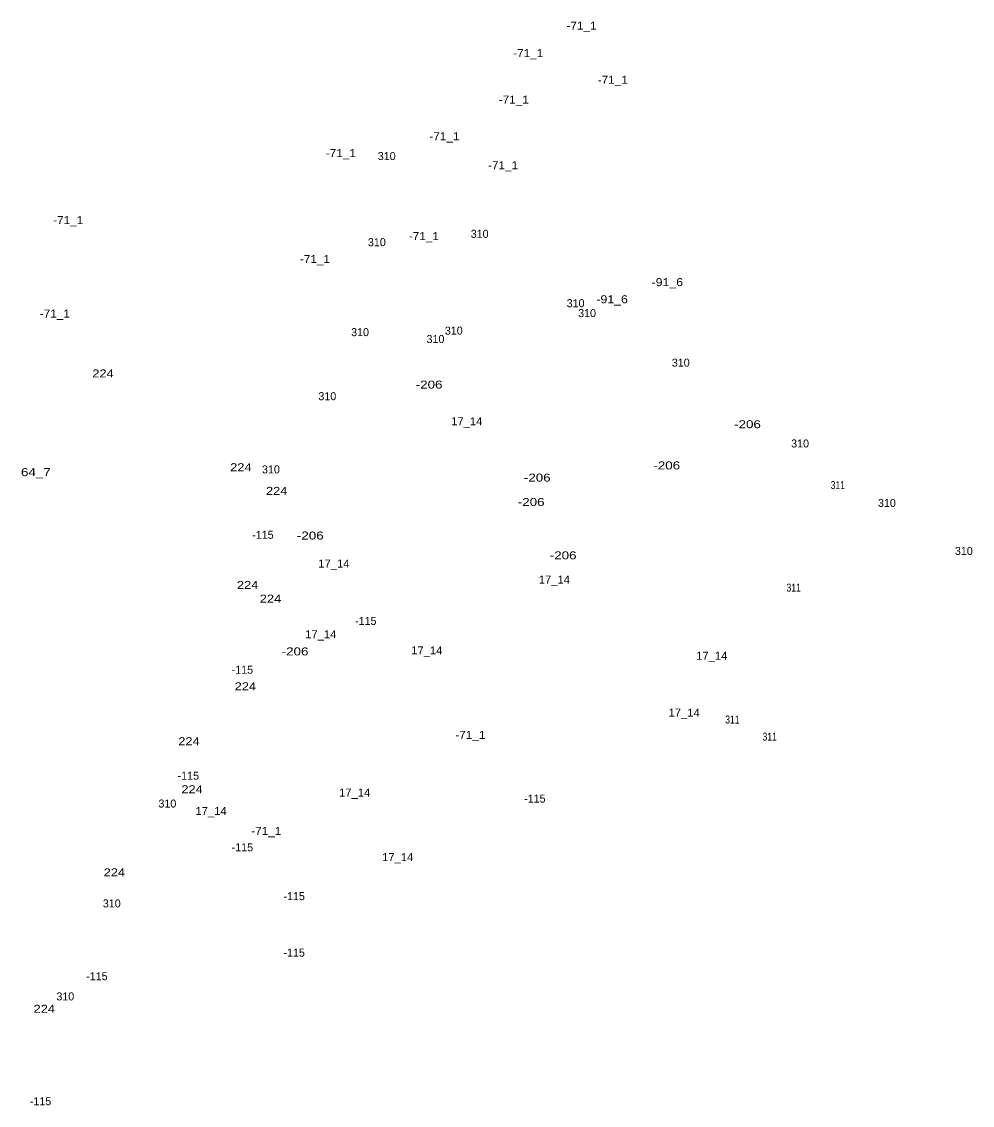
# Model space of a CAD drawing. Extents: x -662996 to -659766, y -998554 to -993949.
# Drawn here: x -660580 to -660105, y -998554 to -998012 of the extents above; entities that cross this region are included whole.
import ezdxf
from ezdxf.enums import TextEntityAlignment as Align

# ---------------------------------------------------------------- set-up
doc = ezdxf.new("R2010")
doc.units = 0
doc.header["$LTSCALE"] = 1.6
doc.layers.add('24', color=7, linetype='Continuous')

msp = doc.modelspace()

# ---------------------------------------------------------------- texts
at = {"layer": '24'}
for s, width, p in [('-71_1', 1.1, (-660299.99, -998016.38)), ('-71_1', 1.1, (-660326.65, -998030.09)), ('-71_1', 1.1, (-660284.38, -998043.43)), ('-71_1', 1.1, (-660333.88, -998053.33)), ('-71_1', 1.1, (-660368.541, -998071.62)), ('-71_1', 1.1, (-660420.331, -998080.05)), ('-71_1', 1.1, (-660339.221, -998086.09)), ('-71_1', 1.1, (-660556.66, -998113.55)), ('-71_1', 1.1, (-660378.821, -998121.52)), ('-71_1', 1.1, (-660433.28, -998132.98)), ('-91_6', 1.15, (-660257.09, -998144.54)), ('-91_6', 1.15, (-660284.69, -998153.09)), ('-71_1', 1.1, (-660563.331, -998160.25)), ('224', 1.2, (-660539.23, -998190.17)), ('-206', 1.25, (-660376.19, -998195.74)), ('17_14', 1.05, (-660357.35, -998214.07)), ('-206', 1.25, (-660217.01, -998215.55)), ('64_7', 1.25, (-660572.81, -998239.49)), ('224', 1.2, (-660470.299, -998237.03)), ('-206', 1.25, (-660257.38, -998236.12)), ('-206', 1.25, (-660322.12, -998242.21)), ('311', 0.8, (-660171.83, -998245.96)), ('224', 1.2, (-660452.4, -998248.84)), ('-206', 1.25, (-660325.16, -998254.41)), ('-206', 1.25, (-660435.6, -998271.17)), ('-206', 1.25, (-660309.17, -998281.07)), ('17_14', 1.05, (-660423.79, -998285.14)), ('17_14', 1.05, (-660313.579, -998293.2)), ('224', 1.2, (-660466.91, -998295.85)), ('311', 0.8, (-660193.92, -998297.19)), ('224', 1.2, (-660455.49, -998302.71)), ('17_14', 1.05, (-660430.319, -998320.48)), ('-206', 1.25, (-660443.22, -998329.07)), ('17_14', 1.05, (-660377.319, -998328.54)), ('17_14', 1.05, (-660234.85, -998331.23)), ('224', 1.2, (-660468.059, -998346.52)), ('17_14', 1.05, (-660248.679, -998359.66)), ('311', 0.8, (-660224.58, -998363.1)), ('-71_1', 1.1, (-660355.561, -998370.76)), ('224', 1.2, (-660496.24, -998373.95)), ('311', 0.8, (-660205.92, -998371.67)), ('224', 1.2, (-660494.709, -998397.95)), ('17_14', 1.05, (-660413.419, -998399.61)), ('17_14', 1.05, (-660485.23, -998408.83)), ('-71_1', 1.1, (-660457.611, -998418.76)), ('17_14', 1.05, (-660391.91, -998431.88)), ('224', 1.2, (-660533.559, -998439.47)), ('224', 1.2, (-660568.59, -998507.66))]:
    msp.add_text(s, height=4, dxfattribs=dict(at, width=width)).set_placement(p, align=Align.CENTER)
for s, p in [('310', (-660397.38, -998081.53)), ('310', (-660350.92, -998120.39)), ('310', (-660402.33, -998124.58)), ('310', (-660302.94, -998155.05)), ('310', (-660297.22, -998160)), ('310', (-660410.71, -998169.53)), ('310', (-660363.87, -998168.77)), ('310', (-660373.01, -998172.96)), ('310', (-660250.38, -998184.77)), ('310', (-660427.08, -998201.53)), ('310', (-660190.71, -998225.15)), ('310', (-660455.26, -998238.1)), ('310', (-660147.3, -998254.86)), ('-115', (-660459.27, -998270.8)), ('310', (-660108.84, -998278.86)), ('-115', (-660407.861, -998313.84)), ('-115', (-660469.551, -998338.22)), ('-115', (-660496.591, -998391.18)), ('-115', (-660323.311, -998402.6)), ('310', (-660507.05, -998405.09)), ('-115', (-660469.551, -998426.99)), ('-115', (-660443.65, -998451.37)), ('310', (-660534.85, -998455)), ('-115', (-660443.65, -998479.56)), ('-115', (-660542.28, -998491.37)), ('310', (-660558.08, -998501.47)), ('-115', (-660570.461, -998553.84))]:
    msp.add_text(s, height=4, dxfattribs=at).set_placement(p, align=Align.CENTER)

doc.saveas('drawing.dxf')
